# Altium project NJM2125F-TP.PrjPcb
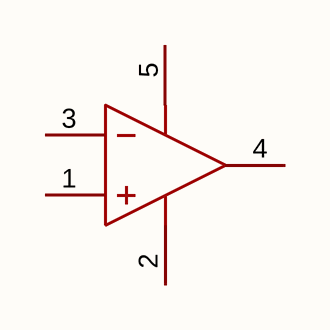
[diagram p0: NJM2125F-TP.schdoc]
1 sheet, 1 parts. Net scope: global (net labels, ports and power ports of the same name join across sheets).

## Sheet NJM2125F-TP.schdoc
size 127 x 101 mm

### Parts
U?  njm2125f-tp  [SOT-23-5_L3.0-W1.7-P0.95-LS2.8-BL]  (value not drawn)

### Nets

Not connected (* = marked no-connect by the designer): U? 1(IN_+) 2(V-) 3(IN_-) 4(OUT) 5(V+)

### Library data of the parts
U? = njm2125f-tp: Manufacturer: TECH PUBLIC(台舟); AddInBom: yes; ModelId: 0a2a1b8f50944f73965918ad6e5fe167; ModelName: SOT-23-5_L2.9-W1.6-H1.1-LS2.8-P0.95; ModelTransform: 118.60433,114.173,0,90,0,0,0.0005,0.0005,0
